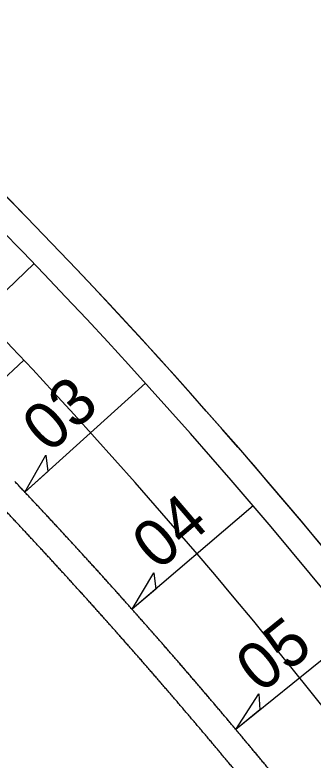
# Model space of a CAD drawing. Extents: x 2167182 to 2168576, y 842635 to 844493.
# Drawn here: x 2167810.5 to 2167855, y 844016.4 to 844127.3 of the extents above; entities that cross this region are included whole.
import ezdxf

# ---------------------------------------------------------------- set-up
doc = ezdxf.new("R2010")
doc.units = 0
for name, color, linetype in [('Prop EOT', 7, 'Continuous'), ('Prop Horizontal Alignment', 7, 'Continuous'), ('Prop Horizontal Alignment Tick Large', 7, 'Continuous'), ('Prop Paved Shoulder', 7, 'Continuous'), ('Prop Shade Light', 7, 'Continuous'), ('Prop Superelevation  Arrow CELL', 7, 'Continuous'), ('Prop Superelevation Label', 7, 'Continuous')]:
    doc.layers.add(name, color=color, linetype=linetype)

msp = doc.modelspace()

# ---------------------------------------------------------------- linework, layer by layer
at = {"layer": 'Prop EOT'}
msp.add_arc((2167204.29, 843506.02), 844, 7.27898, 47.10916, dxfattribs=at)
for points in [[(2167847.24, 844016.37), (2167846.76, 844016.94), (2167846.28, 844017.52), (2167845.8, 844018.1), (2167845.32, 844018.67), (2167844.84, 844019.25), (2167844.36, 844019.82), (2167843.88, 844020.4), (2167843.4, 844020.97), (2167842.92, 844021.54), (2167842.44, 844022.12), (2167841.95, 844022.69), (2167841.47, 844023.26), (2167840.99, 844023.83), (2167840.5, 844024.4), (2167840.02, 844024.97), (2167839.53, 844025.54), (2167839.04, 844026.11), (2167838.56, 844026.68), (2167838.07, 844027.25), (2167837.58, 844027.82), (2167837.09, 844028.39), (2167836.61, 844028.96), (2167836.12, 844029.52), (2167835.63, 844030.09), (2167835.14, 844030.66), (2167834.65, 844031.22), (2167834.16, 844031.79), (2167833.66, 844032.35), (2167833.17, 844032.92), (2167832.68, 844033.48), (2167832.19, 844034.04), (2167831.69, 844034.61), (2167831.2, 844035.17), (2167830.7, 844035.73), (2167830.21, 844036.29), (2167829.71, 844036.85), (2167829.22, 844037.41), (2167828.72, 844037.98), (2167828.22, 844038.53), (2167827.72, 844039.09), (2167827.23, 844039.65), (2167826.73, 844040.21), (2167826.23, 844040.77), (2167825.73, 844041.33), (2167825.23, 844041.88), (2167824.73, 844042.44), (2167824.23, 844043), (2167823.72, 844043.55), (2167823.22, 844044.11), (2167822.72, 844044.66), (2167822.22, 844045.22), (2167821.71, 844045.77), (2167821.21, 844046.32), (2167820.7, 844046.87), (2167820.2, 844047.43), (2167819.69, 844047.98), (2167819.19, 844048.53), (2167818.68, 844049.08), (2167818.17, 844049.63), (2167817.66, 844050.18), (2167817.16, 844050.73), (2167816.65, 844051.28), (2167816.14, 844051.83), (2167815.63, 844052.38), (2167815.12, 844052.92), (2167814.61, 844053.47), (2167814.1, 844054.02), (2167813.58, 844054.56), (2167813.07, 844055.11), (2167812.56, 844055.65), (2167812.05, 844056.2), (2167811.53, 844056.74), (2167811.02, 844057.29), (2167810.51, 844057.83)], [(2167881.13, 843972.46), (2167880.7, 843973.07), (2167880.26, 843973.67), (2167879.82, 843974.28), (2167879.38, 843974.89), (2167878.94, 843975.5), (2167878.5, 843976.1), (2167878.05, 843976.71), (2167877.61, 843977.32), (2167877.17, 843977.92), (2167876.73, 843978.53), (2167876.28, 843979.13), (2167875.84, 843979.74), (2167875.39, 843980.34), (2167874.95, 843980.94), (2167874.5, 843981.55), (2167874.05, 843982.15), (2167873.61, 843982.75), (2167873.16, 843983.35), (2167872.71, 843983.95), (2167872.26, 843984.56), (2167871.81, 843985.16), (2167871.36, 843985.76), (2167870.91, 843986.36), (2167870.46, 843986.95), (2167870.01, 843987.55), (2167869.56, 843988.15), (2167869.11, 843988.75), (2167868.65, 843989.35), (2167868.2, 843989.94), (2167867.75, 843990.54), (2167867.29, 843991.14), (2167866.84, 843991.73), (2167866.38, 843992.33), (2167865.92, 843992.92), (2167865.47, 843993.52), (2167865.01, 843994.11), (2167864.55, 843994.71), (2167864.09, 843995.3), (2167863.63, 843995.89), (2167863.17, 843996.48), (2167862.71, 843997.08), (2167862.25, 843997.67), (2167861.79, 843998.26), (2167861.33, 843998.85), (2167860.87, 843999.44), (2167860.41, 844000.03), (2167859.94, 844000.62), (2167859.48, 844001.21), (2167859.02, 844001.8), (2167858.55, 844002.38), (2167858.09, 844002.97), (2167857.62, 844003.56), (2167857.15, 844004.15), (2167856.69, 844004.73), (2167856.22, 844005.32), (2167855.75, 844005.9), (2167855.28, 844006.49), (2167854.81, 844007.07), (2167854.34, 844007.66), (2167853.87, 844008.24), (2167853.4, 844008.82), (2167852.93, 844009.41), (2167852.46, 844009.99), (2167851.99, 844010.57), (2167851.52, 844011.15), (2167851.04, 844011.73), (2167850.57, 844012.31), (2167850.09, 844012.89), (2167849.62, 844013.47), (2167849.14, 844014.05), (2167848.67, 844014.63), (2167848.19, 844015.21), (2167847.72, 844015.79), (2167847.24, 844016.37)]]:
    msp.add_spline(points, degree=3, dxfattribs=at)
at = {"layer": 'Prop Horizontal Alignment'}
msp.add_arc((2167204.29, 843506.02), 833, 7.27898, 47.10916, dxfattribs=at)
at = {"layer": 'Prop Horizontal Alignment Tick Large'}
msp.add_line((2167811.82, 844075.93), (2167805.99, 844070.46), dxfattribs=at)
at = {"layer": 'Prop Paved Shoulder'}
msp.add_arc((2167204.29, 843506.02), 848, 31.58206, 47.10916, dxfattribs=at)
msp.add_spline([(2167844.16, 844013.81), (2167843.68, 844014.39), (2167843.2, 844014.96), (2167842.73, 844015.54), (2167842.25, 844016.11), (2167841.77, 844016.68), (2167841.3, 844017.25), (2167840.82, 844017.83), (2167840.34, 844018.4), (2167839.86, 844018.97), (2167839.38, 844019.54), (2167838.9, 844020.11), (2167838.42, 844020.68), (2167837.93, 844021.25), (2167837.45, 844021.81), (2167836.97, 844022.38), (2167836.49, 844022.95), (2167836, 844023.52), (2167835.52, 844024.08), (2167835.03, 844024.65), (2167834.55, 844025.22), (2167834.06, 844025.78), (2167833.58, 844026.35), (2167833.09, 844026.91), (2167832.6, 844027.47), (2167832.11, 844028.04), (2167831.63, 844028.6), (2167831.14, 844029.16), (2167830.65, 844029.72), (2167830.16, 844030.29), (2167829.67, 844030.85), (2167829.18, 844031.41), (2167828.69, 844031.97), (2167828.19, 844032.53), (2167827.7, 844033.09), (2167827.21, 844033.65), (2167826.72, 844034.2), (2167826.22, 844034.76), (2167825.73, 844035.32), (2167825.23, 844035.88), (2167824.74, 844036.43), (2167824.24, 844036.99), (2167823.74, 844037.55), (2167823.25, 844038.1), (2167822.75, 844038.65), (2167822.25, 844039.21), (2167821.75, 844039.76), (2167821.26, 844040.32), (2167820.76, 844040.87), (2167820.26, 844041.42), (2167819.76, 844041.97), (2167819.26, 844042.52), (2167818.75, 844043.08), (2167818.25, 844043.63), (2167817.75, 844044.18), (2167817.25, 844044.73), (2167816.74, 844045.27), (2167816.24, 844045.82), (2167815.74, 844046.37), (2167815.23, 844046.92), (2167814.73, 844047.47), (2167814.22, 844048.01), (2167813.71, 844048.56), (2167813.21, 844049.11), (2167812.7, 844049.65), (2167812.19, 844050.2), (2167811.68, 844050.74), (2167811.18, 844051.28), (2167810.67, 844051.83), (2167810.16, 844052.37), (2167809.65, 844052.91), (2167809.14, 844053.45), (2167808.63, 844054), (2167808.11, 844054.54), (2167807.6, 844055.08)], degree=3, dxfattribs=at)
at = {"layer": 'Prop Shade Light'}
for radius, start in [(848, 16.19989), (844, 7.27898)]:
    msp.add_arc((2167204.29, 843506.02), radius, start, 47.10916, dxfattribs=at)
for points in [[(2167810.51, 844057.83), (2167810.68, 844057.65), (2167810.85, 844057.47), (2167811.02, 844057.29), (2167811.19, 844057.11), (2167811.36, 844056.92), (2167811.53, 844056.74), (2167811.7, 844056.56), (2167811.88, 844056.38), (2167812.05, 844056.2), (2167812.22, 844056.02), (2167812.39, 844055.84), (2167812.56, 844055.65), (2167812.73, 844055.47), (2167812.9, 844055.29), (2167813.07, 844055.11), (2167813.24, 844054.93), (2167813.41, 844054.74), (2167813.58, 844054.56), (2167813.76, 844054.38), (2167813.93, 844054.2), (2167814.1, 844054.02), (2167814.27, 844053.83), (2167814.44, 844053.65), (2167814.61, 844053.47), (2167814.78, 844053.29), (2167814.95, 844053.11), (2167815.12, 844052.92), (2167815.29, 844052.74), (2167815.46, 844052.56), (2167815.63, 844052.38), (2167815.8, 844052.19), (2167815.97, 844052.01), (2167816.14, 844051.83), (2167816.31, 844051.65), (2167816.48, 844051.46), (2167816.65, 844051.28), (2167816.82, 844051.1), (2167816.99, 844050.91), (2167817.16, 844050.73), (2167817.33, 844050.55), (2167817.49, 844050.36), (2167817.66, 844050.18), (2167817.83, 844050), (2167818, 844049.81), (2167818.17, 844049.63), (2167818.34, 844049.45), (2167818.51, 844049.26), (2167818.68, 844049.08), (2167818.85, 844048.9), (2167819.02, 844048.71), (2167819.19, 844048.53), (2167819.35, 844048.35), (2167819.52, 844048.16), (2167819.69, 844047.98), (2167819.86, 844047.79), (2167820.03, 844047.61), (2167820.2, 844047.43), (2167820.37, 844047.24), (2167820.53, 844047.06), (2167820.7, 844046.87), (2167820.87, 844046.69), (2167821.04, 844046.51), (2167821.21, 844046.32), (2167821.38, 844046.14), (2167821.54, 844045.95), (2167821.71, 844045.77), (2167821.88, 844045.58), (2167822.05, 844045.4), (2167822.22, 844045.22), (2167822.38, 844045.03), (2167822.55, 844044.85), (2167822.72, 844044.66), (2167822.83, 844044.54), (2167822.95, 844044.41), (2167823.06, 844044.29)], [(2167823.06, 844044.29), (2167823.11, 844044.23), (2167823.17, 844044.17), (2167823.22, 844044.11), (2167823.39, 844043.92), (2167823.56, 844043.74), (2167823.72, 844043.55), (2167823.89, 844043.37), (2167824.06, 844043.18), (2167824.23, 844043), (2167824.39, 844042.81), (2167824.56, 844042.63), (2167824.73, 844042.44), (2167824.89, 844042.25), (2167825.06, 844042.07), (2167825.23, 844041.88), (2167825.39, 844041.7), (2167825.56, 844041.51), (2167825.73, 844041.33), (2167825.89, 844041.14), (2167826.06, 844040.96), (2167826.23, 844040.77), (2167826.39, 844040.58), (2167826.56, 844040.4), (2167826.73, 844040.21), (2167826.89, 844040.03), (2167827.06, 844039.84), (2167827.23, 844039.65), (2167827.39, 844039.47), (2167827.56, 844039.28), (2167827.72, 844039.09), (2167827.89, 844038.91), (2167828.06, 844038.72), (2167828.22, 844038.53), (2167828.39, 844038.35), (2167828.55, 844038.16), (2167828.72, 844037.98), (2167828.88, 844037.79), (2167829.05, 844037.6), (2167829.22, 844037.41), (2167829.38, 844037.23), (2167829.55, 844037.04), (2167829.71, 844036.85), (2167829.88, 844036.67), (2167830.04, 844036.48), (2167830.21, 844036.29), (2167830.37, 844036.11), (2167830.54, 844035.92), (2167830.7, 844035.73), (2167830.87, 844035.54), (2167831.03, 844035.36), (2167831.2, 844035.17), (2167831.36, 844034.98), (2167831.53, 844034.79), (2167831.69, 844034.61), (2167831.86, 844034.42), (2167832.02, 844034.23), (2167832.19, 844034.04), (2167832.35, 844033.86), (2167832.51, 844033.67), (2167832.68, 844033.48), (2167832.84, 844033.29), (2167833.01, 844033.1), (2167833.17, 844032.92), (2167833.34, 844032.73), (2167833.5, 844032.54), (2167833.66, 844032.35), (2167833.83, 844032.16), (2167833.99, 844031.98), (2167834.16, 844031.79), (2167834.32, 844031.6), (2167834.48, 844031.41), (2167834.65, 844031.22), (2167834.81, 844031.03), (2167834.97, 844030.85), (2167835.14, 844030.66), (2167835.19, 844030.59), (2167835.25, 844030.53), (2167835.31, 844030.46)], [(2167832.28, 844027.84), (2167832.23, 844027.91), (2167832.17, 844027.97), (2167832.11, 844028.04), (2167831.95, 844028.22), (2167831.79, 844028.41), (2167831.63, 844028.6), (2167831.46, 844028.79), (2167831.3, 844028.98), (2167831.14, 844029.16), (2167830.97, 844029.35), (2167830.81, 844029.54), (2167830.65, 844029.72), (2167830.48, 844029.91), (2167830.32, 844030.1), (2167830.16, 844030.29), (2167829.99, 844030.47), (2167829.83, 844030.66), (2167829.67, 844030.85), (2167829.5, 844031.03), (2167829.34, 844031.22), (2167829.18, 844031.41), (2167829.01, 844031.59), (2167828.85, 844031.78), (2167828.69, 844031.97), (2167828.52, 844032.15), (2167828.36, 844032.34), (2167828.19, 844032.53), (2167828.03, 844032.71), (2167827.87, 844032.9), (2167827.7, 844033.09), (2167827.54, 844033.27), (2167827.37, 844033.46), (2167827.21, 844033.65), (2167827.04, 844033.83), (2167826.88, 844034.02), (2167826.72, 844034.2), (2167826.55, 844034.39), (2167826.39, 844034.58), (2167826.22, 844034.76), (2167826.06, 844034.95), (2167825.89, 844035.13), (2167825.73, 844035.32), (2167825.56, 844035.51), (2167825.4, 844035.69), (2167825.23, 844035.88), (2167825.07, 844036.06), (2167824.9, 844036.25), (2167824.74, 844036.43), (2167824.57, 844036.62), (2167824.41, 844036.8), (2167824.24, 844036.99), (2167824.08, 844037.17), (2167823.91, 844037.36), (2167823.74, 844037.55), (2167823.58, 844037.73), (2167823.41, 844037.92), (2167823.25, 844038.1), (2167823.08, 844038.29), (2167822.92, 844038.47), (2167822.75, 844038.65), (2167822.58, 844038.84), (2167822.42, 844039.02), (2167822.25, 844039.21), (2167822.09, 844039.39), (2167821.92, 844039.58), (2167821.75, 844039.76), (2167821.59, 844039.95), (2167821.42, 844040.13), (2167821.26, 844040.32), (2167821.09, 844040.5), (2167820.92, 844040.68), (2167820.76, 844040.87), (2167820.59, 844041.05), (2167820.42, 844041.24), (2167820.26, 844041.42), (2167820.2, 844041.48), (2167820.15, 844041.54), (2167820.1, 844041.6)], [(2167835.31, 844030.46), (2167835.41, 844030.34), (2167835.52, 844030.21), (2167835.63, 844030.09), (2167835.79, 844029.9), (2167835.95, 844029.71), (2167836.12, 844029.52), (2167836.28, 844029.33), (2167836.44, 844029.15), (2167836.61, 844028.96), (2167836.77, 844028.77), (2167836.93, 844028.58), (2167837.09, 844028.39), (2167837.26, 844028.2), (2167837.42, 844028.01), (2167837.58, 844027.82), (2167837.75, 844027.63), (2167837.91, 844027.44), (2167838.07, 844027.25), (2167838.23, 844027.06), (2167838.4, 844026.87), (2167838.56, 844026.68), (2167838.72, 844026.49), (2167838.88, 844026.3), (2167839.04, 844026.11), (2167839.21, 844025.92), (2167839.37, 844025.73), (2167839.53, 844025.54), (2167839.69, 844025.35), (2167839.85, 844025.16), (2167840.02, 844024.97), (2167840.18, 844024.78), (2167840.34, 844024.59), (2167840.5, 844024.4), (2167840.66, 844024.21), (2167840.82, 844024.02), (2167840.99, 844023.83), (2167841.15, 844023.64), (2167841.31, 844023.45), (2167841.47, 844023.26), (2167841.63, 844023.07), (2167841.79, 844022.88), (2167841.95, 844022.69), (2167842.11, 844022.5), (2167842.28, 844022.31), (2167842.44, 844022.12), (2167842.6, 844021.93), (2167842.76, 844021.73), (2167842.92, 844021.54), (2167843.08, 844021.35), (2167843.24, 844021.16), (2167843.4, 844020.97), (2167843.56, 844020.78), (2167843.72, 844020.59), (2167843.88, 844020.4), (2167844.04, 844020.2), (2167844.2, 844020.01), (2167844.36, 844019.82), (2167844.52, 844019.63), (2167844.68, 844019.44), (2167844.84, 844019.25), (2167845, 844019.06), (2167845.16, 844018.86), (2167845.32, 844018.67), (2167845.48, 844018.48), (2167845.64, 844018.29), (2167845.8, 844018.1), (2167845.96, 844017.9), (2167846.12, 844017.71), (2167846.28, 844017.52), (2167846.44, 844017.33), (2167846.6, 844017.14), (2167846.76, 844016.94), (2167846.92, 844016.75), (2167847.08, 844016.56), (2167847.24, 844016.37)]]:
    msp.add_open_spline(points, degree=3, dxfattribs=at)
at = {"layer": 'Prop Superelevation  Arrow CELL'}
for p, q in [((2167813.37, 844090.28), (2167795.56, 844073.19)), ((2167829.95, 844072.49), (2167812.01, 844056.24)), ((2167846.01, 844054.23), (2167827.97, 844038.82)), ((2167861.54, 844035.51), (2167843.43, 844020.93))]:
    msp.add_line(p, q, dxfattribs=at)
for points in [[(2167812.01, 844056.24), (2167815.11, 844061.75), (2167815.43, 844059.35)], [(2167827.97, 844038.82), (2167831.23, 844044.24), (2167831.49, 844041.82)], [(2167843.43, 844020.93), (2167846.85, 844026.25), (2167847.03, 844023.83)]]:
    msp.add_lwpolyline(points, close=True, dxfattribs=at)

# ---------------------------------------------------------------- texts
at = {"layer": 'Prop Superelevation Label'}
for s, rotation, p in [('03', 42.157, (2167815.62, 844061.87)), ('04', 40.5062, (2167831.83, 844044.42)), ('05', 38.8555, (2167847.12, 844026.15))]:
    msp.add_text(s, height=7, rotation=rotation, dxfattribs=at).set_placement(p)

doc.saveas('drawing.dxf')
